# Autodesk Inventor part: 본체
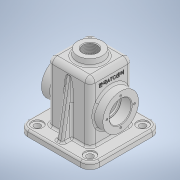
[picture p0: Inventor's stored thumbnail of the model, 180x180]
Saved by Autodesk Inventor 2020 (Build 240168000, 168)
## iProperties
Created: 2021-07
Part Number: 본체
Material: 일반
Document SubType Name: Modeling
Designer: Owner
Density: 1 g/cm^3
Appearance: 기본값
Mass: 278.252 g
Surface Area: 858.264 cm^2
Volume: 278.252 cm^3
Author: Owner
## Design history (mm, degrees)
sketch "스케치1"
  geometry: L1 (34, -34)-(-34, -34); L2 (-34, -34)-(-34, 34); L3 (-34, 34)-(34, 34); L4 (34, 34)-(34, -34); L5 (34, -34)-(-34, 34); L6 (-34, -34)-(34, 34); 1 further point
  constraints: 12 end point, 2 midpoint, 2 parallel, 1 horizontal, 1 perpendicular
  dimensions: "d0" = 68 distance of L2.end L3.end; "d1" = 68 distance of L1.end L2.end
extrude "돌출1" new body sketch "스케치1" distance "d2" = 105; taper "d3" = 0 deg
fillet "모깎기1" dims "d4" = 8
fillet "모깎기2" dims "d5" = 8
feature "쉘1" dims "d6" = 5
node "작업 평면1"
sketch "스케치2"
  geometry: C1 r 20 at (0, 0); 1 further point
  constraints: 1 centre point, 1 coincident
  dimensions: "d8" = 40 diameter of C1
extrude "돌출2" join sketch "스케치2" stored distance "d9" = 105; taper "d10" = 8 deg
sketch "스케치4"
  geometry: L1 (-57, -57)-(57, -57); L2 (57, -57)-(57, 57); L3 (57, 57)-(-57, 57); L4 (-57, 57)-(-57, -57); L5 (-57, -57)-(57, 57); L6 (57, -57)-(-57, 57); L7 (-26, 34)-(26, 34) reference; L8 (-34, -26)-(-34, 26) reference; L9 (26, -34)-(-26, -34) reference; L10 (34, 26)-(34, -26) reference; L11 (-26, 29)-(26, 29) reference; L12 (29, 26)-(29, -26) reference; L13 (26, -29)-(-26, -29) reference; L14 (-29, -26)-(-29, 26) reference; A1 r 8 centre (-26, 26) between (-26, 34) and (-34, 26) reference; A2 r 8 centre (-26, -26) between (-34, -26) and (-26, -34) reference; A3 r 8 centre (26, -26) between (26, -34) and (34, -26) reference; A4 r 8 centre (26, 26) between (34, 26) and (26, 34) reference; A5 r 3 centre (26, 26) between (29, 26) and (26, 29) reference; A6 r 3 centre (26, -26) between (26, -29) and (29, -26) reference; A7 r 3 centre (-26, -26) between (-29, -26) and (-26, -29) reference; A8 r 3 centre (-26, 26) between (-26, 29) and (-29, 26) reference; 1 further point
  constraints: 12 end point, 2 midpoint, 2 parallel, 1 horizontal, 1 perpendicular
  dimensions: "d11" = 114 distance of L3.end L2.end; "d12" = 114 distance of L2.end L1.end
extrude "돌출3" join sketch "스케치4" distance "d13" = 10; taper "d14" = 0 deg
node "작업 평면2"
sketch "스케치6"
  geometry: L1 (26, -97)-(26, 44.872); L2 (83, -97)-(-31, -97) reference; C1 r 28.5 at (26, -45)
  constraints: 2 end point, 1 centre point, 1 point on line, 1 vertical
  dimensions: "d20" = 57 diameter of C1; "d21" = 52 distance from line of L2 C1.centre
extrude "돌출5" join sketch "스케치6" stored distance "d22" = 15; taper "d23" = 0 deg
sketch "스케치7"
  geometry: C1 r 28.5 at (0, 0) reference; C2 r 17.5 at (0, 0); 1 further point
  constraints: 1 centre point, 1 coincident
  dimensions: "d24" = 35 diameter of C2
extrude "돌출6" cut sketch "스케치7" distance "d25" = 17; taper "d26" = 0 deg
sketch "스케치8"
  geometry: C1 r 17.5 at (0, 0) reference; C2 r 15 at (0, 0); 1 further point
  constraints: 1 centre point, 1 coincident
  dimensions: "d27" = 30 diameter of C2
extrude "돌출7" cut sketch "스케치8" distance "d28" = 3; taper "d29" = 0 deg
sketch "스케치9" dims "d30" = 44
  geometry: C1 r 28.5 at (0, 0) reference; C2 r 15 at (0, 0) reference; 3 further points
  constraints: 1 coincident, 1 vertical alignment, 2 other
hole "구멍1" sketch "스케치9" at (0, 22) diameter "d31" = 3.242; stored, may be unused: countersink angle "d35" = 90 deg, drill point angle "d37" = 118 deg; dims "d32" = 8, "d33" = 4, "d34" = 2, "d36" = 10
sketch "스케치10"
  geometry: C1 r 20 at (0, 0) reference; 1 further point
sketch "스케치11"
  geometry: C1 r 20 at (0, 0) reference; 2 further points
  constraints: 1 coincident
hole "구멍2" sketch "스케치11" at (0, 0) diameter "d41" = 22.83494; stored, may be unused: countersink angle "d45" = 90 deg, drill point angle "d47" = 118 deg; dims "d42" = 28.25, "d43" = 4, "d44" = 2, "d46" = 59.3
sketch "스케치12"
  geometry: L1 (43.42, 43.107)-(10, 49); L2 (10, 57)-(10, -57) reference; L3 (0, 57)-(10, 57) reference; 1 further point
  constraints: 2 end point, 1 point on line
  dimensions: "d48" = 8 distance from line of L3 L1.end; "d49" = 100 deg angle of L2 L1
feature "리브1" sketch "스케치12" dims "d50" = 1, "d51" = 10, "d52" = 0, "d53" = 0, "d54" = 1, "d55" = 1
fillet "모깎기3" dims "d56" = 15
sketch "스케치13"
  geometry: C1 r 9 at (-42, -42); A1 r 15 centre (-42, -42) between (-57, -42) and (-42, -57) reference; 1 further point
  constraints: 1 centre point, 1 coincident
  dimensions: "d57" = 18 diameter of C1
extrude "돌출8" cut sketch "스케치13" distance "d58" = 2; taper "d59" = 0 deg
sketch "스케치14"
  geometry: C1 r 9 at (0, 0) reference; C2 r 9 at (0, 0) reference; C3 r 5 at (0, 0); 1 further point
  constraints: 1 centre point, 1 coincident
  dimensions: "d60" = 10 diameter of C3
extrude "돌출9" cut sketch "스케치14" stored distance "d61" = 2; taper "d62" = 0 deg
fillet "모깎기4" dims "d63" = 3
fillet "모깎기5" dims "d64" = 3
fillet "모깎기7" dims "d66" = 3
chamfer "모따기1" distance "d67" = 1; stored, may be unused: second distance "d68" = 2, angle "d69" = 45 deg
chamfer "모따기2" distance "d70" = 1; stored, may be unused: second distance "d71" = 2, angle "d72" = 45 deg
chamfer "모따기3" distance "d73" = 1; stored, may be unused: second distance "d74" = 2, angle "d75" = 45 deg
fillet "모깎기8" dims "d76" = 3
fillet "모깎기9" dims "d77" = 3
fillet "모깎기10" dims "d78" = 3
sketch "스케치15"
  geometry: L1 (6, 18)-(46, 18) reference; L2 (60, -84)-(60, 0) reference; 2 further points
  constraints: 1 other
  dimensions: "d79" = 25 distance from line of L1 point (26, -7); "d80" = 34 distance from line of L2 point (26, -7)
feature "엠보싱1" sketch "스케치15" dims "d81" = 0.5, "d82" = 0
fillet "모깎기13" dims "d85" = 0.3
node "솔리드1"
pattern_circular "원형 패턴1" dims angle "d39" = 360 deg
mirror "미러1"
mirror "미러2"
mirror "미러3"
mirror "미러4"
node "투영된 루프1"
feature "A9D066F2-1C7D-4E18-AEED-F7BC21143FA4" dims "d41" = 22.83494, "d42" = 28.25, "d43" = 4, "d44" = 2, "d45" = 90 deg, "d46" = 59.3, "d47" = 118 deg
other parameters: "d7" = -115, "d19" = 15
